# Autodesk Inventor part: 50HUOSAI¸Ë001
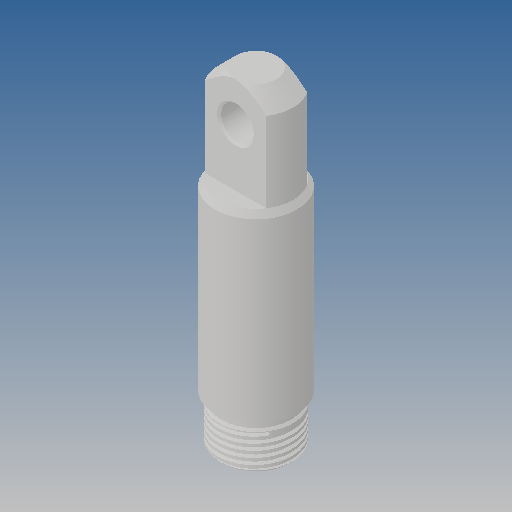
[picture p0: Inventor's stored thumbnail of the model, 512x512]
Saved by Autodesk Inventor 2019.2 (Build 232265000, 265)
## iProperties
Created: 2013-07
Part Number: 50HUOSAI¸Ë001
Material: Ogólny
Document SubType Name: Modeling
Designer: CADENGINEERING4
Density: 1 g/cm^3
Appearance: Domyślna
Author: CADENGINEERING4
Revision Number: ÈÎºÎ
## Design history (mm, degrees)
feature "ÇÐ³ý-É¨Ãè1"
node "Bryła1"
